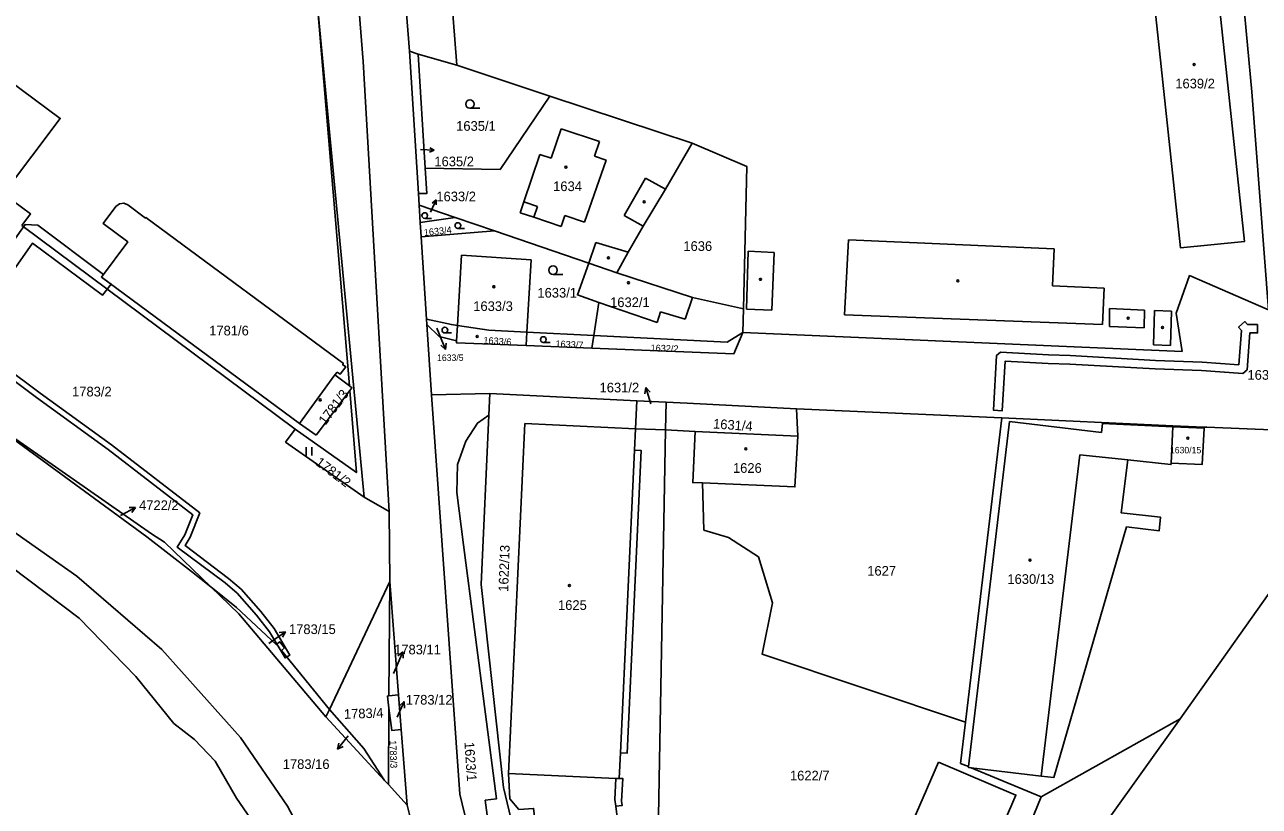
# Model space of a CAD drawing. Extents: x -756746 to -753363, y -1166406 to -1161727.
# Drawn here: x -755813.4 to -755596.6, y -1164079.2 to -1163941.9 of the extents above; entities that cross this region are included whole.
import ezdxf

# ---------------------------------------------------------------- set-up
doc = ezdxf.new("R2010")
doc.units = 0
for name, color, linetype in [('Hranice parcel', 7, 'Continuous'), ('Parcelní čísla', 7, 'Continuous'), ('Pop  PČ popisy', 7, 'Continuous'), ('Vnitřní kresba', 7, 'Continuous'), ('Věcná břemena k části', 7, 'Continuous'), ('Značky budov', 7, 'Continuous'), ('Značky kultur', 7, 'Continuous')]:
    doc.layers.add(name, color=color, linetype=linetype)

msp = doc.modelspace()

# ---------------------------------------------------------------- linework, layer by layer
at = {"layer": 'Hranice parcel'}
for p, q in [((-755743.34, -1163872.33), (-755737.54, -1163948.99)), ((-755756.36, -1164005.31), (-755762.08, -1163937.18)), ((-755762.08, -1163937.18), (-755753.77, -1164024.87)), ((-755745.81, -1163946.5), (-755744.27, -1163971.53)), ((-755745.81, -1163946.5), (-755744.29, -1163947.03)), ((-755744.29, -1163947.03), (-755743.05, -1163967.05)), ((-755744.29, -1163947.03), (-755737.54, -1163948.99)), ((-755721.16, -1163954.4), (-755737.54, -1163948.99)), ((-755744.27, -1163971.53), (-755744.16, -1163973.58)), ((-755744.16, -1163973.58), (-755743.96, -1163976.63)), ((-755737.78, -1163975.75), (-755744.16, -1163973.58)), ((-755743.96, -1163976.63), (-755737.78, -1163975.75)), ((-755743.96, -1163976.63), (-755743.79, -1163979.13)), ((-755737.78, -1163975.75), (-755730.92, -1163978.09)), ((-755813.9, -1163977.11), (-755765.91, -1164012.89)), ((-755730.92, -1163978.09), (-755743.79, -1163979.13)), ((-755730.92, -1163978.09), (-755714.35, -1163983.74)), ((-755743.79, -1163979.13), (-755742.82, -1163993.59)), ((-755737.42, -1163994.7), (-755736.7, -1163982.35)), ((-755736.7, -1163982.35), (-755724.46, -1163983.15)), ((-755724.46, -1163983.15), (-755725.19, -1163995.85)), ((-755714.35, -1163983.74), (-755709.41, -1163985.43)), ((-755765.18, -1164011.9), (-755799.94, -1163986.2)), ((-755712.55, -1163990.65), (-755713.46, -1163996.44)), ((-755687.3, -1163995.9), (-755687.18, -1163991.8)), ((-755742.82, -1163993.59), (-755742.76, -1163994.55)), ((-755742.76, -1163994.55), (-755741.94, -1164006.89)), ((-755737.58, -1163997.37), (-755737.42, -1163994.7)), ((-755725.33, -1163998.22), (-755725.19, -1163995.85)), ((-755725.19, -1163995.85), (-755713.46, -1163996.44)), ((-755713.81, -1163998.7), (-755725.33, -1163998.22)), ((-755713.46, -1163996.44), (-755713.81, -1163998.7)), ((-755758.93, -1164003.39), (-755765.18, -1164011.9)), ((-755758.54, -1164002.87), (-755758.93, -1164003.39)), ((-755758.93, -1164003.39), (-755756.36, -1164005.31)), ((-755756.29, -1164006.12), (-755762.23, -1164013.99)), ((-755731.73, -1164006.67), (-755741.94, -1164006.89)), ((-755731.9, -1164010.43), (-755731.73, -1164006.67)), ((-755731.73, -1164006.67), (-755705.92, -1164007.92)), ((-755705.92, -1164007.92), (-755706.13, -1164012.86)), ((-755700.77, -1164008.19), (-755705.92, -1164007.92)), ((-755700.86, -1164013.04), (-755700.77, -1164008.19)), ((-755700.77, -1164008.19), (-755697.06, -1164008.35)), ((-755697.06, -1164008.35), (-755677.83, -1164009.36)), ((-755641.8, -1164010.94), (-755677.83, -1164009.36)), ((-755677.83, -1164009.36), (-755677.6, -1164014.12)), ((-755648.15, -1164064.38), (-755641.8, -1164010.94)), ((-755611.74, -1164012.31), (-755641.8, -1164010.94)), ((-755765.91, -1164012.89), (-755767.62, -1164015.22)), ((-755762.23, -1164013.99), (-755765.18, -1164011.9)), ((-755700.86, -1164013.04), (-755706.13, -1164012.86)), ((-755704.02, -1164189.84), (-755700.86, -1164013.04)), ((-755695.66, -1164013.32), (-755700.86, -1164013.04)), ((-755677.6, -1164014.12), (-755695.66, -1164013.32)), ((-755606.24, -1164012.56), (-755611.74, -1164012.31)), ((-755767.62, -1164015.22), (-755753.77, -1164024.87)), ((-755753.77, -1164024.87), (-755749.42, -1164027.4)), ((-755749.42, -1164027.4), (-755749.28, -1164039.67)), ((-755759.91, -1164062.14), (-755749.28, -1164039.67)), ((-755749.43, -1164059.77), (-755749.28, -1164039.67)), ((-755749.28, -1164039.67), (-755747.75, -1164059.57)), ((-755775.82, -1164045.36), (-755780.73, -1164040.62)), ((-755760.53, -1164063.45), (-755775.82, -1164045.36)), ((-755768.34, -1164051.78), (-755759.91, -1164062.14)), ((-755749.43, -1164059.77), (-755747.75, -1164059.57)), ((-755747.27, -1164065.65), (-755747.75, -1164059.57)), ((-755760.53, -1164063.45), (-755759.91, -1164062.14)), ((-755750.22, -1164074.61), (-755760.53, -1164063.45)), ((-755749.54, -1164075.35), (-755749.44, -1164061.93)), ((-755747.27, -1164065.65), (-755746.23, -1164078.93)), ((-755610.44, -1164063.8), (-755634.87, -1164077.5)), ((-755634.87, -1164077.5), (-755647.17, -1164072.39)), ((-755749.54, -1164075.35), (-755750.22, -1164074.61)), ((-755749.54, -1164075.35), (-755746.23, -1164078.93)), ((-755642.35, -1164095.85), (-755634.87, -1164077.5)), ((-755746.23, -1164078.93), (-755742.93, -1164092.21))]:
    msp.add_line(p, q, dxfattribs=at)
for points in [[(-755745.81, -1163946.5), (-755754.44, -1163838.14), (-755759.37, -1163816.57)], [(-755761.66, -1163851.85), (-755753.95, -1163948.32), (-755749.42, -1164027.4)], [(-755889.91, -1163898.92), (-755889.22, -1163898), (-755894.17, -1163894.29), (-755889.13, -1163887.57), (-755874.43, -1163898.52), (-755863.15, -1163883.34), (-755857.21, -1163880.69), (-755811.01, -1163914.93), (-755812.86, -1163917.45), (-755810.31, -1163919.33), (-755827.83, -1163943.04), (-755807.18, -1163958.32), (-755817.15, -1163971.58), (-755812.4, -1163975.09), (-755813.9, -1163977.11)], [(-755616.92, -1163920.06), (-755610.4, -1163981.05), (-755599.13, -1163979.92), (-755605.67, -1163918.96)], [(-755600.05, -1163934.11), (-755599.38, -1163937.21), (-755597.85, -1163953.64), (-755594.94, -1163991.94)], [(-755721.16, -1163954.4), (-755729.93, -1163967.28), (-755743.05, -1163967.05)], [(-755696.19, -1163962.67), (-755702.21, -1163960.66), (-755721.16, -1163954.4)], [(-755709.41, -1163985.43), (-755707.4, -1163981.84), (-755704.8, -1163977.23), (-755700.88, -1163970.74), (-755696.19, -1163962.67)], [(-755687.18, -1163991.8), (-755686.57, -1163966.79), (-755696.19, -1163962.67)], [(-755743.05, -1163967.05), (-755742.78, -1163971.5), (-755744.27, -1163971.53)], [(-755799.94, -1163986.2), (-755795.32, -1163980.01), (-755799.64, -1163976.79), (-755797.42, -1163973.81), (-755796.76, -1163973.3), (-755796.03, -1163973.23), (-755795.33, -1163973.51), (-755792.21, -1163975.83), (-755792.12, -1163975.71), (-755757.43, -1164001.36), (-755757.58, -1164001.57), (-755757.03, -1164001.95), (-755758.01, -1164003.27), (-755758.54, -1164002.87)], [(-755714.35, -1163983.74), (-755716.34, -1163989.33), (-755712.55, -1163990.65)], [(-755709.41, -1163985.43), (-755696.13, -1163989.8), (-755687.18, -1163991.8)], [(-755594.94, -1163991.94), (-755608.8, -1163985.94), (-755611.17, -1163992.56), (-755610.13, -1163999.24), (-755687.3, -1163995.9)], [(-755742.82, -1163993.59), (-755738.47, -1163994.54), (-755737.42, -1163994.7)], [(-755737.58, -1163997.37), (-755740.59, -1163996.66), (-755742.76, -1163994.55)], [(-755737.42, -1163994.7), (-755731.91, -1163995.5), (-755725.19, -1163995.85)], [(-755687.3, -1163995.9), (-755688.85, -1163999.67), (-755713.81, -1163998.7)], [(-755713.46, -1163996.44), (-755690.04, -1163997.63), (-755687.3, -1163995.9)], [(-755725.33, -1163998.22), (-755737.6, -1163997.73), (-755737.58, -1163997.37)], [(-755765.91, -1164012.89), (-755755.14, -1164020.55), (-755756.29, -1164006.12)], [(-755756.29, -1164006.12), (-755755.93, -1164005.63), (-755756.36, -1164005.31)], [(-755741.94, -1164006.89), (-755736.96, -1164077.02), (-755719.45, -1164149.69), (-755708.59, -1164192.59)], [(-755823.76, -1164008.55), (-755791.14, -1164031.27), (-755788.88, -1164032.77), (-755780.73, -1164040.62)], [(-755780.73, -1164040.62), (-755784.1, -1164037.92), (-755791.99, -1164031.81), (-755823.76, -1164008.55)], [(-755730.1, -1164089.58), (-755732.18, -1164080.72), (-755732.53, -1164078.09), (-755730.52, -1164077.82), (-755736.36, -1164033.22), (-755737.53, -1164024.04), (-755737.39, -1164019.1), (-755735.96, -1164015.03), (-755733.86, -1164011.85), (-755731.9, -1164010.43)], [(-755721.16, -1164109.86), (-755729.29, -1164075.84), (-755733.22, -1164040.21), (-755731.9, -1164010.43)], [(-755706.13, -1164012.86), (-755725.55, -1164011.93), (-755728.41, -1164073.4)], [(-755706.13, -1164012.86), (-755706.3, -1164016.6), (-755705.12, -1164016.66), (-755707.59, -1164069.8), (-755708.77, -1164069.75), (-755708.98, -1164074.28)], [(-755694.38, -1164022.35), (-755696.08, -1164022.28), (-755695.66, -1164013.32)], [(-755612.05, -1164018.89), (-755611.75, -1164012.48), (-755611.74, -1164012.31)], [(-755606.24, -1164012.56), (-755606.23, -1164012.73), (-755606.58, -1164019.09), (-755612.05, -1164018.89)], [(-755491.82, -1164064.42), (-755496.88, -1164060.86), (-755498.88, -1164060.15), (-755508.05, -1164053.73), (-755511.75, -1164050.28), (-755558.21, -1164017.57), (-755574.58, -1164013.87), (-755605.78, -1164012.58), (-755606.24, -1164012.56)], [(-755694.38, -1164022.35), (-755678.14, -1164023.04), (-755677.6, -1164014.12)], [(-755612.05, -1164018.89), (-755612.07, -1164019.13), (-755619.67, -1164018.3), (-755620.82, -1164027.59), (-755613.88, -1164028.38), (-755614.13, -1164030.75), (-755619.87, -1164030.09), (-755632.67, -1164074.1), (-755634.88, -1164073.85), (-755647.17, -1164072.39)], [(-755830.02, -1164020.65), (-755804.24, -1164038.74), (-755789.32, -1164051.62), (-755775.49, -1164067.09), (-755767.26, -1164079.15), (-755757.86, -1164096.93), (-755754.53, -1164109.21), (-755750.56, -1164123.85)], [(-755648.15, -1164064.38), (-755683.89, -1164052.42), (-755682.08, -1164043.41), (-755684.53, -1164035.35), (-755689.78, -1164031.92), (-755694.12, -1164030.64), (-755694.38, -1164022.35)], [(-755610.44, -1164063.8), (-755593.11, -1164039.34), (-755588.6, -1164032.96), (-755511.48, -1164087.8), (-755522.53, -1164103.41), (-755533.32, -1164118.53)], [(-755780.73, -1164040.62), (-755776.24, -1164044.23), (-755769.24, -1164050.76), (-755768.63, -1164050.26), (-755767.79, -1164051.3), (-755768.34, -1164051.78)], [(-755749.44, -1164061.93), (-755749.71, -1164059.8), (-755749.43, -1164059.77)], [(-755759.91, -1164062.14), (-755753.83, -1164069.01), (-755750.22, -1164074.61)], [(-755749.44, -1164061.93), (-755748.96, -1164065.82), (-755747.27, -1164065.65)], [(-755647.17, -1164072.39), (-755647.66, -1164072.33), (-755647.64, -1164072.19), (-755649.01, -1164071.62), (-755648.15, -1164064.38)], [(-755533.32, -1164118.53), (-755558.38, -1164153.61), (-755635.48, -1164098.74), (-755610.44, -1164063.8)], [(-755652.92, -1164071.4), (-755658.89, -1164085.19), (-755645.28, -1164091.05), (-755639.31, -1164077.2), (-755652.92, -1164071.4)], [(-755708.98, -1164074.28), (-755709.58, -1164074.27), (-755728.41, -1164073.4)], [(-755728.41, -1164073.4), (-755728.2, -1164077.86), (-755726.61, -1164079.69), (-755724.02, -1164079.52), (-755720.24, -1164109.73)], [(-755708.98, -1164074.28), (-755708.33, -1164074.28), (-755708.56, -1164078.26), (-755708.47, -1164078.99), (-755709.61, -1164079.13), (-755708.4, -1164088.71), (-755707.46, -1164088.59), (-755706.39, -1164097.12), (-755707.33, -1164097.23), (-755705.95, -1164108.11)]]:
    msp.add_lwpolyline(points, dxfattribs=at)
at = {"layer": 'Pop  PČ popisy'}
for p, q in [((-755741.47, -1163963.89), (-755742.26, -1163963.47)), ((-755743.87, -1163963.81), (-755741.47, -1163963.89)), ((-755741.47, -1163963.89), (-755742.29, -1163964.27)), ((-755742.13, -1163974.8), (-755741.17, -1163972.63)), ((-755741.17, -1163972.63), (-755741.85, -1163973.2)), ((-755741.17, -1163972.63), (-755741.13, -1163973.52)), ((-755741.01, -1163995.18), (-755740.62, -1163996.14)), ((-755740.62, -1163996.14), (-755739.5, -1163998.92)), ((-755739.5, -1163998.92), (-755740.33, -1163998.18)), ((-755739.5, -1163998.92), (-755739.41, -1163997.81)), ((-755704.32, -1164005.59), (-755704.5, -1164006.69)), ((-755703.44, -1164008.46), (-755704.32, -1164005.59)), ((-755704.32, -1164005.59), (-755703.55, -1164006.4)), ((-755796.61, -1164028.09), (-755793.98, -1164026.64)), ((-755793.98, -1164026.64), (-755795.1, -1164026.68)), ((-755793.98, -1164026.64), (-755794.62, -1164027.56)), ((-755770.53, -1164050.54), (-755770.06, -1164050.21)), ((-755770.06, -1164050.21), (-755767.6, -1164048.49)), ((-755767.6, -1164048.49), (-755768.71, -1164048.65)), ((-755767.6, -1164048.49), (-755768.14, -1164049.47)), ((-755748.18, -1164054.76), (-755747.01, -1164052)), ((-755747.01, -1164052), (-755747.86, -1164052.72)), ((-755747.01, -1164052), (-755746.94, -1164053.11)), ((-755748.63, -1164055.84), (-755748.18, -1164054.76)), ((-755747.97, -1164063.51), (-755746.75, -1164060.77)), ((-755746.75, -1164060.77), (-755747.61, -1164061.48)), ((-755746.75, -1164060.77), (-755746.7, -1164061.89)), ((-755756.62, -1164066.77), (-755758.47, -1164069.14)), ((-755758.47, -1164069.14), (-755758.25, -1164068.04)), ((-755758.47, -1164069.14), (-755757.46, -1164068.65))]:
    msp.add_line(p, q, dxfattribs=at)
at = {"layer": 'Vnitřní kresba'}
for p, q in [((-755720.96, -1163965.33), (-755719.21, -1163960.14)), ((-755719.21, -1163960.14), (-755712.44, -1163962.4)), ((-755712.44, -1163962.4), (-755713.32, -1163964.95)), ((-755725.72, -1163973), (-755722.92, -1163964.67)), ((-755722.92, -1163964.67), (-755720.96, -1163965.33)), ((-755711.31, -1163965.64), (-755715.1, -1163976.56)), ((-755713.32, -1163964.95), (-755711.31, -1163965.64)), ((-755704.36, -1163968.83), (-755708.12, -1163975.36)), ((-755700.88, -1163970.74), (-755704.36, -1163968.83)), ((-755726.36, -1163974.89), (-755725.72, -1163973)), ((-755725.72, -1163973), (-755723.35, -1163973.79)), ((-755723.35, -1163973.79), (-755724.01, -1163975.68)), ((-755724.01, -1163975.68), (-755726.36, -1163974.89)), ((-755719.18, -1163977.3), (-755724.01, -1163975.68)), ((-755718.53, -1163975.38), (-755719.18, -1163977.3)), ((-755715.1, -1163976.56), (-755718.53, -1163975.38)), ((-755708.12, -1163975.36), (-755704.8, -1163977.23)), ((-755713.12, -1163980.13), (-755714.35, -1163983.74)), ((-755707.4, -1163981.84), (-755713.12, -1163980.13)), ((-755669.43, -1163992.83), (-755668.73, -1163979.65)), ((-755668.73, -1163979.65), (-755632.56, -1163981.22)), ((-755686.63, -1163991.83), (-755686.32, -1163981.65)), ((-755686.32, -1163981.65), (-755681.8, -1163981.87)), ((-755681.8, -1163981.87), (-755682.19, -1163992.02)), ((-755632.56, -1163981.22), (-755632.85, -1163987.72)), ((-755697.42, -1163993.56), (-755696.13, -1163989.8)), ((-755632.85, -1163987.72), (-755623.79, -1163988.13)), ((-755623.79, -1163988.13), (-755624.07, -1163994.53)), ((-755712.55, -1163990.65), (-755702.34, -1163994.16)), ((-755682.19, -1163992.02), (-755686.63, -1163991.83)), ((-755622.87, -1163991.71), (-755622.88, -1163994.87)), ((-755616.73, -1163991.99), (-755622.87, -1163991.71)), ((-755702.34, -1163994.16), (-755701.73, -1163992.32)), ((-755701.73, -1163992.32), (-755697.42, -1163993.56)), ((-755624.07, -1163994.53), (-755669.43, -1163992.83)), ((-755616.77, -1163995.09), (-755616.73, -1163991.99)), ((-755615.13, -1163998.09), (-755614.94, -1163992.08)), ((-755614.94, -1163992.08), (-755611.96, -1163992.17)), ((-755611.96, -1163992.17), (-755612.16, -1163998.19)), ((-755622.88, -1163994.87), (-755616.77, -1163995.09)), ((-755612.16, -1163998.19), (-755615.13, -1163998.09)), ((-755647.64, -1164072.19), (-755640.42, -1164011.56)), ((-755640.42, -1164011.56), (-755624.28, -1164013.49)), ((-755624.28, -1164013.49), (-755624.1, -1164011.93)), ((-755624.1, -1164011.93), (-755611.75, -1164012.48)), ((-755611.75, -1164012.48), (-755606.23, -1164012.73)), ((-755708.77, -1164069.75), (-755706.3, -1164016.6)), ((-755634.88, -1164073.85), (-755628.08, -1164017.39)), ((-755628.08, -1164017.39), (-755619.67, -1164018.3)), ((-755709.75, -1164077.98), (-755709.58, -1164074.27)), ((-755709.61, -1164079.13), (-755709.75, -1164077.98))]:
    msp.add_line(p, q, dxfattribs=at)
at = {"layer": 'Věcná břemena k části'}
for points in [[(-755851.94, -1163972.5), (-755853.55, -1163974.86), (-755847.12, -1163979.26), (-755832.95, -1163989.7), (-755825.76, -1163995.01), (-755823.64, -1163994.32), (-755820.81, -1163990.93), (-755818.08, -1163988.81), (-755812.05, -1163980.22), (-755799.74, -1163989.35), (-755798.26, -1163987.44), (-755799.94, -1163986.2), (-755799.6, -1163985.75), (-755811.12, -1163977.09), (-755813.35, -1163976.97), (-755820.32, -1163986.75), (-755822, -1163988.06), (-755825.15, -1163992.31)], [(-755596.85, -1163994.51), (-755598.62, -1163994.51), (-755599.07, -1163994.01), (-755600.19, -1163995.01), (-755599.7, -1163995.56), (-755600.17, -1164001.6), (-755606.61, -1164001.13), (-755614.79, -1164000.84), (-755629.8, -1163999.98), (-755633.59, -1163999.87), (-755642.02, -1163999.41), (-755642.7, -1163999.94), (-755643.23, -1164009.6), (-755641.73, -1164009.7), (-755641.22, -1164000.98), (-755633.65, -1164001.37), (-755629.86, -1164001.48), (-755614.85, -1164002.34), (-755606.72, -1164002.63), (-755599.46, -1164003.16), (-755598.69, -1164002.47), (-755598.21, -1163996.01), (-755596.85, -1163996.01)]]:
    msp.add_lwpolyline(points, close=True, dxfattribs=at)
for points in [[(-755824.6, -1163997.45), (-755811.34, -1164007.32), (-755798.78, -1164016.46), (-755783.88, -1164027.98), (-755785.27, -1164031.45), (-755786.62, -1164033.65), (-755778.22, -1164039.92), (-755776.11, -1164041.71), (-755772.69, -1164045.59), (-755770.45, -1164048.51), (-755767.69, -1164053.09), (-755766.83, -1164052.59), (-755769.61, -1164047.95), (-755771.93, -1164044.95), (-755775.41, -1164040.99), (-755777.62, -1164039.12), (-755785.24, -1164033.32), (-755784.37, -1164031.89), (-755782.66, -1164027.62), (-755798.18, -1164015.66), (-755810.68, -1164006.58), (-755823.98, -1163996.67)], [(-755815.83, -1164037.09), (-755803.83, -1164046.09), (-755793.89, -1164056.34), (-755787.22, -1164064.6), (-755783.59, -1164067.44), (-755779.94, -1164071.25), (-755776.19, -1164077.73), (-755772.47, -1164083.19), (-755769.66, -1164082.5), (-755764.36, -1164090.12), (-755760.37, -1164097.27), (-755755.55, -1164107.99), (-755754.18, -1164111.02), (-755752.8, -1164116.95), (-755751.63, -1164121.94), (-755751.07, -1164123.82), (-755750.61, -1164123.65), (-755757.86, -1164096.93), (-755767.26, -1164079.15), (-755775.49, -1164067.09), (-755789.32, -1164051.62), (-755804.24, -1164038.74), (-755830.02, -1164020.65)]]:
    msp.add_lwpolyline(points, dxfattribs=at)
at = {"layer": 'Značky budov'}
for centre in [(-755608, -1163948.86), (-755718.34, -1163966.89), (-755704.59, -1163972.98), (-755710.9, -1163982.82), (-755707.37, -1163987.18), (-755684.19, -1163986.59), (-755649.52, -1163986.84), (-755731.02, -1163987.88), (-755619.59, -1163993.4), (-755613.55, -1163995.04), (-755733.94, -1163996.62), (-755761.52, -1164007.78), (-755609.1, -1164014.51), (-755686.77, -1164016.38), (-755636.83, -1164035.9), (-755717.75, -1164040.38)]:
    msp.add_circle(centre, 0.175, dxfattribs=at)
at = {"layer": 'Značky kultur'}
for p, q in [((-755735.21, -1163956.55), (-755733.46, -1163956.55)), ((-755743.16, -1163975.9), (-755741.98, -1163975.9)), ((-755737.33, -1163977.65), (-755736.15, -1163977.65)), ((-755720.62, -1163985.72), (-755718.87, -1163985.72)), ((-755739.6, -1163996.01), (-755738.43, -1163996.01)), ((-755722.32, -1163997.67), (-755721.14, -1163997.67)), ((-755763.96, -1164017.55), (-755763.96, -1164016.05)), ((-755762.96, -1164017.55), (-755762.96, -1164016.05))]:
    msp.add_line(p, q, dxfattribs=at)
for centre, radius in [((-755735.21, -1163955.8), 0.75), ((-755743.16, -1163975.4), 0.502), ((-755737.33, -1163977.15), 0.502), ((-755720.62, -1163984.97), 0.75), ((-755739.61, -1163995.51), 0.502), ((-755722.32, -1163997.17), 0.502)]:
    msp.add_circle(centre, radius, dxfattribs=at)

# ---------------------------------------------------------------- texts
at = {"layer": 'Parcelní čísla'}
for s, height, p in [('1639/2', 1.7, (-755611.31, -1163953.05)), ('1635/1', 1.7, (-755737.63, -1163960.5)), ('1635/2', 1.7, (-755741.46, -1163966.73)), ('1634', 1.7, (-755720.6, -1163971.09)), ('1633/2', 1.7, (-755741.11, -1163972.88)), ('1636', 1.7, (-755697.72, -1163981.6)), ('1633/1', 1.7, (-755723.36, -1163989.8)), ('1632/1', 1.7, (-755710.59, -1163991.47)), ('1633/3', 1.7, (-755734.63, -1163992.15)), ('1781/6', 1.7, (-755781.01, -1163996.44)), ('1633/5', 1.139, (-755740.99, -1164000.93)), ('1631/1', 1.7, (-755598.63, -1164004.23)), ('1631/2', 1.7, (-755712.44, -1164006.45)), ('1783/2', 1.7, (-755805.1, -1164007.16)), ('1630/15', 1.139, (-755612.25, -1164017.16)), ('1626', 1.7, (-755689.01, -1164020.58)), ('4722/2', 1.7, (-755793.33, -1164027.12)), ('1627', 1.7, (-755665.42, -1164038.64)), ('1630/13', 1.7, (-755640.8, -1164040.09)), ('1625', 1.7, (-755719.74, -1164044.66)), ('1783/15', 1.7, (-755767, -1164048.9)), ('1783/11', 1.7, (-755748.53, -1164052.47)), ('1783/12', 1.7, (-755746.48, -1164061.29)), ('1783/16', 1.7, (-755768.09, -1164072.6)), ('1622/7', 1.7, (-755679, -1164074.61))]:
    msp.add_text(s, height=height, dxfattribs=at).set_placement(p)
for s, height, rotation, p in [('1633/4', 1.2, 6, (-755743.25, -1163978.98)), ('1633/6', 1.2, 356, (-755732.88, -1163997.86)), ('1633/7', 1.2, 357, (-755720.21, -1163998.5)), ('1632/2', 1.2, 358, (-755703.5, -1163999.23)), ('1781/3', 1.7, 53, (-755760.58, -1164012.31)), ('1631/4', 1.7, 356, (-755692.55, -1164012.78)), ('1781/2', 1.7, 323, (-755762.5, -1164019.05)), ('1622/13', 1.7, 88, (-755728.5, -1164041.49)), ('1783/4', 1.7, 2, (-755757.32, -1164063.81)), ('1783/3', 1.2, 272, (-755749.35, -1164067.58)), ('1623/1', 1.7, 274, (-755736.19, -1164067.9))]:
    msp.add_text(s, height=height, rotation=rotation, dxfattribs=at).set_placement(p)

doc.saveas('drawing.dxf')
